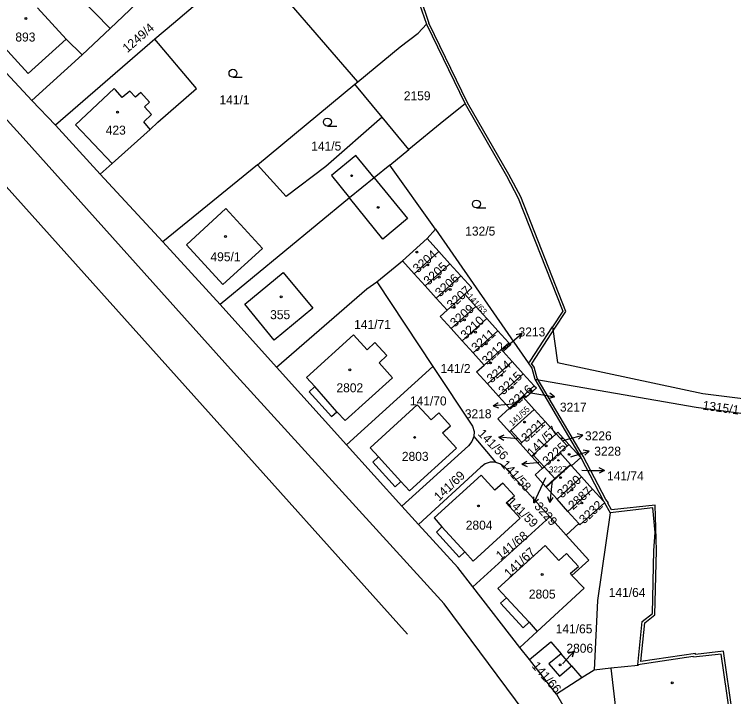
# Model space of a CAD drawing. Extents: x -866656 to -858817, y -1041816 to -1038653.
# Drawn here: x -866311.9 to -866175.7, y -1039421.3 to -1039292.1 of the extents above; entities that cross this region are included whole.
import ezdxf

# ---------------------------------------------------------------- set-up
doc = ezdxf.new("R2010")
doc.units = 0
for name, color, linetype in [('Hranice parcel', 7, 'Continuous'), ('Parcelní čísla', 7, 'Continuous'), ('Pop  PČ popisy', 7, 'Continuous'), ('Vnitřní kresba', 7, 'Continuous'), ('Značky budov', 7, 'Continuous'), ('Značky kultur', 7, 'Continuous')]:
    doc.layers.add(name, color=color, linetype=linetype)

msp = doc.modelspace()

# ---------------------------------------------------------------- linework, layer by layer
at = {"layer": 'Hranice parcel'}
for p, q in [((-866310.19, -1039315.5), (-866388.17, -1039229.96)), ((-866243.86, -1039264.43), (-866233.84, -1039293.98)), ((-866246.83, -1039304.89), (-866267.13, -1039281.27)), ((-866293.75, -1039294.78), (-866302.19, -1039286.07)), ((-866293.75, -1039294.78), (-866286.54, -1039287.95)), ((-866273.98, -1039287.22), (-866281.75, -1039293.82)), ((-866324.37, -1039291.52), (-866308.57, -1039308.43)), ((-866281.75, -1039293.82), (-866285.25, -1039296.84)), ((-866235.43, -1039295.7), (-866233.84, -1039293.98)), ((-866233.84, -1039293.98), (-866226.5, -1039309.08)), ((-866317.38, -1039294.43), (-866309.25, -1039303.3)), ((-866299.04, -1039299.78), (-866293.75, -1039294.78)), ((-866238.82, -1039298.26), (-866235.43, -1039295.7)), ((-866309.25, -1039303.3), (-866302.07, -1039296.79)), ((-866285.25, -1039296.84), (-866304.12, -1039313.11)), ((-866302.07, -1039296.79), (-866299.04, -1039299.78)), ((-866277.39, -1039306.13), (-866285.25, -1039296.84)), ((-866246.83, -1039304.89), (-866238.82, -1039298.26)), ((-866308.57, -1039308.43), (-866299.04, -1039299.78)), ((-866247.38, -1039305.34), (-866246.83, -1039304.89)), ((-866284.74, -1039312.51), (-866277.39, -1039306.13)), ((-866265.81, -1039320.6), (-866247.38, -1039305.34)), ((-866242.2, -1039311.59), (-866247.38, -1039305.34)), ((-866304.12, -1039313.11), (-866308.57, -1039308.43)), ((-866226.5, -1039309.08), (-866230.52, -1039312.29)), ((-866226.5, -1039309.08), (-866218.65, -1039322.67)), ((-866242.2, -1039311.59), (-866252.88, -1039320.93)), ((-866237.17, -1039317.71), (-866242.2, -1039311.59)), ((-866286.15, -1039313.91), (-866284.74, -1039312.51)), ((-866230.52, -1039312.29), (-866237.17, -1039317.71)), ((-866304.12, -1039313.11), (-866295.62, -1039322.36)), ((-866293.38, -1039320.36), (-866286.15, -1039313.91)), ((-866270.38, -1039359.88), (-866310.19, -1039315.5)), ((-866240.77, -1039320.64), (-866237.17, -1039317.71)), ((-866316.84, -1039320.96), (-866237.43, -1039409.44)), ((-866295.62, -1039322.36), (-866293.38, -1039320.36)), ((-866265.81, -1039320.6), (-866283.77, -1039335.19)), ((-866260.41, -1039326.6), (-866265.81, -1039320.6)), ((-866252.88, -1039320.93), (-866260.41, -1039326.6)), ((-866240.77, -1039320.64), (-866243.73, -1039323.05)), ((-866232.15, -1039332.75), (-866240.77, -1039320.64)), ((-866295.62, -1039322.36), (-866283.77, -1039335.19)), ((-866243.73, -1039323.05), (-866248.4, -1039326.86)), ((-866218.65, -1039322.67), (-866216.44, -1039326.88)), ((-866248.4, -1039326.86), (-866272.92, -1039347.03)), ((-866216.44, -1039326.88), (-866208.01, -1039348.3)), ((-866233.7, -1039334.53), (-866232.15, -1039332.75)), ((-866232.15, -1039332.75), (-866214.57, -1039358.1)), ((-866238.36, -1039338.78), (-866233.7, -1039334.53)), ((-866233.7, -1039334.53), (-866231.47, -1039337.01)), ((-866283.77, -1039335.19), (-866272.92, -1039347.03)), ((-866236.16, -1039341.22), (-866231.47, -1039337.01)), ((-866231.47, -1039337.01), (-866229.4, -1039339.31)), ((-866243.22, -1039342.74), (-866238.36, -1039338.78)), ((-866236.16, -1039341.22), (-866238.36, -1039338.78)), ((-866234.09, -1039343.52), (-866229.4, -1039339.31)), ((-866229.4, -1039339.31), (-866227.33, -1039341.62)), ((-866234.09, -1039343.52), (-866236.16, -1039341.22)), ((-866232.01, -1039345.83), (-866227.33, -1039341.62)), ((-866227.33, -1039341.62), (-866225.22, -1039343.89)), ((-866245.13, -1039344.04), (-866243.22, -1039342.74)), ((-866243.22, -1039342.74), (-866232.63, -1039358.74)), ((-866262.24, -1039358.91), (-866245.13, -1039344.04)), ((-866232.01, -1039345.83), (-866234.09, -1039343.52)), ((-866225.22, -1039343.89), (-866226.56, -1039345.09)), ((-866229.9, -1039348.1), (-866226.56, -1039345.09)), ((-866226.56, -1039345.09), (-866224.48, -1039347.39)), ((-866272.92, -1039347.03), (-866262.24, -1039358.91)), ((-866229.9, -1039348.1), (-866232.01, -1039345.83)), ((-866231.24, -1039349.3), (-866229.9, -1039348.1)), ((-866229.16, -1039351.6), (-866224.48, -1039347.39)), ((-866224.48, -1039347.39), (-866222.4, -1039349.69)), ((-866208.01, -1039348.3), (-866209.97, -1039351.26)), ((-866229.16, -1039351.6), (-866231.24, -1039349.3)), ((-866227.08, -1039353.9), (-866222.4, -1039349.69)), ((-866222.4, -1039349.69), (-866220.32, -1039351.99)), ((-866227.08, -1039353.9), (-866229.16, -1039351.6)), ((-866225, -1039356.2), (-866220.32, -1039351.99)), ((-866220.32, -1039351.99), (-866218.24, -1039354.29)), ((-866214.2, -1039357.79), (-866209.97, -1039351.26)), ((-866209.97, -1039351.26), (-866209.02, -1039358.03)), ((-866247.68, -1039352.75), (-866256.57, -1039360.83)), ((-866245.05, -1039355.62), (-866247.68, -1039352.75)), ((-866225, -1039356.2), (-866227.08, -1039353.9)), ((-866243.59, -1039354.25), (-866245.05, -1039355.62)), ((-866241.37, -1039356.71), (-866243.59, -1039354.25)), ((-866219.66, -1039355.54), (-866218.24, -1039354.29)), ((-866217.87, -1039354.6), (-866219.31, -1039355.92)), ((-866218.24, -1039354.29), (-866217.87, -1039354.6)), ((-866222.92, -1039358.49), (-866225, -1039356.2)), ((-866222.92, -1039358.49), (-866219.66, -1039355.54)), ((-866219.31, -1039355.92), (-866219.66, -1039355.54)), ((-866219.31, -1039355.92), (-866217.58, -1039357.84)), ((-866242.8, -1039358.06), (-866241.37, -1039356.71)), ((-866222.25, -1039362.07), (-866217.58, -1039357.84)), ((-866217.58, -1039357.84), (-866215.5, -1039360.14)), ((-866214.57, -1039358.1), (-866214.2, -1039357.79)), ((-866209.02, -1039358.03), (-866181.49, -1039363.87)), ((-866249, -1039373.58), (-866262.24, -1039358.91)), ((-866232.63, -1039358.74), (-866249, -1039373.58)), ((-866240.26, -1039360.9), (-866242.8, -1039358.06)), ((-866232.63, -1039358.74), (-866225.12, -1039370.08)), ((-866224.33, -1039359.77), (-866222.92, -1039358.49)), ((-866214.57, -1039358.1), (-866213.9, -1039359.11)), ((-866213.9, -1039359.11), (-866213.3, -1039361.19)), ((-866230.48, -1039403.71), (-866270.38, -1039359.88)), ((-866222.25, -1039362.07), (-866224.33, -1039359.77)), ((-866220.17, -1039364.37), (-866215.5, -1039360.14)), ((-866215.5, -1039360.14), (-866213.42, -1039362.44)), ((-866256.57, -1039360.83), (-866255, -1039362.57)), ((-866249.2, -1039369.02), (-866240.26, -1039360.9)), ((-866220.17, -1039364.37), (-866222.25, -1039362.07)), ((-866213.3, -1039361.19), (-866204.6, -1039375.99)), ((-866213.3, -1039361.19), (-866182.74, -1039366.49)), ((-866255, -1039362.57), (-866256.07, -1039363.56)), ((-866215.64, -1039364.45), (-866213.42, -1039362.44)), ((-866213.02, -1039362.81), (-866215.02, -1039364.62)), ((-866213.42, -1039362.44), (-866213.02, -1039362.81)), ((-866256.07, -1039363.56), (-866251.84, -1039368.26)), ((-866218.09, -1039366.67), (-866220.17, -1039364.37)), ((-866218.09, -1039366.67), (-866215.64, -1039364.45)), ((-866215.51, -1039364.6), (-866217.96, -1039366.82)), ((-866215.51, -1039364.6), (-866215.64, -1039364.45)), ((-866215.25, -1039364.37), (-866215.51, -1039364.6)), ((-866213.43, -1039366.9), (-866215.51, -1039364.6)), ((-866215.02, -1039364.62), (-866215.25, -1039364.37)), ((-866181.49, -1039363.87), (-866150.56, -1039367.7)), ((-866235.57, -1039366.05), (-866244.47, -1039374.16)), ((-866232.97, -1039368.85), (-866235.57, -1039366.05)), ((-866251.84, -1039368.26), (-866250.78, -1039367.33)), ((-866250.78, -1039367.33), (-866249.2, -1039369.02)), ((-866231.48, -1039367.56), (-866232.97, -1039368.85)), ((-866229.28, -1039370.02), (-866231.48, -1039367.56)), ((-866220.32, -1039368.68), (-866218.09, -1039366.67)), ((-866217.96, -1039366.82), (-866218.09, -1039366.67)), ((-866217.83, -1039370.88), (-866213.43, -1039366.9)), ((-866213.43, -1039366.9), (-866211.35, -1039369.2)), ((-866182.74, -1039366.49), (-866151.75, -1039370.52)), ((-866218.1, -1039371.12), (-866220.32, -1039368.68)), ((-866230.77, -1039371.35), (-866229.28, -1039370.02)), ((-866225.12, -1039370.08), (-866224.82, -1039371.05)), ((-866211.35, -1039369.2), (-866215.74, -1039373.17)), ((-866209.27, -1039371.49), (-866211.35, -1039369.2)), ((-866228.16, -1039374.22), (-866230.77, -1039371.35)), ((-866224.82, -1039371.05), (-866224.86, -1039372.05)), ((-866218.1, -1039371.12), (-866217.83, -1039370.88)), ((-866216.02, -1039373.42), (-866218.1, -1039371.12)), ((-866215.74, -1039373.17), (-866217.83, -1039370.88)), ((-866213.65, -1039375.46), (-866209.27, -1039371.49)), ((-866209.27, -1039371.49), (-866208.97, -1039371.22)), ((-866207.19, -1039373.79), (-866209.27, -1039371.49)), ((-866208.97, -1039371.22), (-866206.88, -1039373.51)), ((-866225.22, -1039372.99), (-866225.88, -1039373.76)), ((-866224.86, -1039372.05), (-866225.22, -1039372.99)), ((-866224.86, -1039372.05), (-866220.77, -1039376.85)), ((-866238.47, -1039385.18), (-866249, -1039373.58)), ((-866244.47, -1039374.16), (-866242.9, -1039375.89)), ((-866225.88, -1039373.76), (-866238.47, -1039385.18)), ((-866237.06, -1039382.29), (-866228.16, -1039374.22)), ((-866216.02, -1039373.42), (-866215.74, -1039373.17)), ((-866213.94, -1039375.72), (-866216.02, -1039373.42)), ((-866208.6, -1039375.07), (-866207.19, -1039373.79)), ((-866207.19, -1039373.79), (-866206.88, -1039373.51)), ((-866206.88, -1039373.51), (-866204.6, -1039375.99)), ((-866213.94, -1039375.72), (-866213.65, -1039375.46)), ((-866211.86, -1039378.02), (-866213.94, -1039375.72)), ((-866211.56, -1039377.75), (-866213.65, -1039375.46)), ((-866211.56, -1039377.75), (-866208.6, -1039375.07)), ((-866206.58, -1039377.3), (-866208.6, -1039375.07)), ((-866242.9, -1039375.89), (-866243.99, -1039376.9)), ((-866243.99, -1039376.9), (-866239.75, -1039381.55)), ((-866221.77, -1039376.86), (-866222.73, -1039377.22)), ((-866220.77, -1039376.85), (-866221.77, -1039376.86)), ((-866220.77, -1039376.85), (-866219.83, -1039377.19)), ((-866204.6, -1039375.99), (-866206.34, -1039377.57)), ((-866204.6, -1039375.99), (-866200.28, -1039384.26)), ((-866223.51, -1039377.82), (-866235.33, -1039388.65)), ((-866222.73, -1039377.22), (-866223.51, -1039377.82)), ((-866219.83, -1039377.19), (-866219.02, -1039377.84)), ((-866219.02, -1039377.84), (-866210.49, -1039387.25)), ((-866213.27, -1039379.3), (-866211.86, -1039378.02)), ((-866211.86, -1039378.02), (-866211.56, -1039377.75)), ((-866209.54, -1039379.97), (-866211.56, -1039377.75)), ((-866211.19, -1039381.59), (-866206.52, -1039377.37)), ((-866209.54, -1039379.97), (-866206.58, -1039377.3)), ((-866206.52, -1039377.37), (-866206.58, -1039377.3)), ((-866206.34, -1039377.57), (-866206.52, -1039377.37)), ((-866204.44, -1039379.66), (-866206.34, -1039377.57)), ((-866223.48, -1039379.34), (-866232.4, -1039387.42)), ((-866220.87, -1039382.15), (-866223.48, -1039379.34)), ((-866211.25, -1039381.53), (-866213.27, -1039379.3)), ((-866204.44, -1039379.66), (-866209.11, -1039383.89)), ((-866202.36, -1039381.96), (-866204.44, -1039379.66)), ((-866239.75, -1039381.55), (-866238.66, -1039380.53)), ((-866238.66, -1039380.53), (-866237.06, -1039382.29)), ((-866219.4, -1039380.86), (-866220.87, -1039382.15)), ((-866217.17, -1039383.26), (-866219.4, -1039380.86)), ((-866211.25, -1039381.53), (-866209.54, -1039379.97)), ((-866211.19, -1039381.59), (-866211.25, -1039381.53)), ((-866209.11, -1039383.89), (-866211.19, -1039381.59)), ((-866207.03, -1039386.19), (-866202.36, -1039381.96)), ((-866202.36, -1039381.96), (-866200.28, -1039384.26)), ((-866218.71, -1039384.56), (-866217.17, -1039383.26)), ((-866207.03, -1039386.19), (-866209.11, -1039383.89)), ((-866235.33, -1039388.65), (-866238.47, -1039385.18)), ((-866216.06, -1039387.48), (-866218.71, -1039384.56)), ((-866200.12, -1039384.55), (-866204.8, -1039388.73)), ((-866200.28, -1039384.26), (-866200.06, -1039384.5)), ((-866200.06, -1039384.5), (-866200.12, -1039384.55)), ((-866200.12, -1039384.55), (-866199.07, -1039386.46)), ((-866204.95, -1039388.49), (-866207.03, -1039386.19)), ((-866199.07, -1039386.46), (-866201.43, -1039403.06)), ((-866190.99, -1039385.55), (-866199.07, -1039386.46)), ((-866190.53, -1039390.22), (-866190.99, -1039385.55)), ((-866232.4, -1039387.42), (-866230.9, -1039389.15)), ((-866210.49, -1039387.25), (-866225.06, -1039400.48)), ((-866224.97, -1039395.59), (-866216.06, -1039387.48)), ((-866210.49, -1039387.25), (-866207.37, -1039390.68)), ((-866227.92, -1039396.82), (-866235.33, -1039388.65)), ((-866230.9, -1039389.15), (-866231.91, -1039390.16)), ((-866207.37, -1039390.68), (-866204.95, -1039388.49)), ((-866204.8, -1039388.73), (-866204.95, -1039388.49)), ((-866231.91, -1039390.16), (-866227.65, -1039394.84)), ((-866207.37, -1039390.68), (-866203.09, -1039395.4)), ((-866190.77, -1039393.59), (-866190.53, -1039390.22)), ((-866211.37, -1039392.68), (-866220.32, -1039400.77)), ((-866208.79, -1039395.52), (-866211.37, -1039392.68)), ((-866227.65, -1039394.84), (-866226.54, -1039393.86)), ((-866226.54, -1039393.86), (-866224.97, -1039395.59)), ((-866207.32, -1039394.17), (-866208.79, -1039395.52)), ((-866205.07, -1039396.62), (-866207.32, -1039394.17)), ((-866191.05, -1039405.53), (-866190.77, -1039393.59)), ((-866203.09, -1039395.4), (-866206.31, -1039398.32)), ((-866225.06, -1039400.48), (-866227.92, -1039396.82)), ((-866206.57, -1039397.9), (-866205.07, -1039396.62)), ((-866206.31, -1039398.32), (-866206.57, -1039397.9)), ((-866203.95, -1039400.75), (-866206.31, -1039398.32)), ((-866216.12, -1039411.94), (-866225.06, -1039400.48)), ((-866220.32, -1039400.77), (-866218.69, -1039402.54)), ((-866212.84, -1039408.95), (-866203.95, -1039400.75)), ((-866218.69, -1039402.54), (-866219.8, -1039403.55)), ((-866215.35, -1039424.06), (-866230.48, -1039403.71)), ((-866219.8, -1039403.55), (-866215.54, -1039408.21)), ((-866201.43, -1039403.06), (-866202.07, -1039416.25)), ((-866192.95, -1039407.03), (-866191.05, -1039405.53)), ((-866193.78, -1039415.23), (-866192.95, -1039407.03)), ((-866215.54, -1039408.21), (-866214.4, -1039407.15)), ((-866214.4, -1039407.15), (-866212.84, -1039408.95)), ((-866212.84, -1039408.95), (-866216.12, -1039411.94)), ((-866214.31, -1039414.26), (-866210.31, -1039410.87)), ((-866210.31, -1039410.87), (-866208.35, -1039413.14)), ((-866214.31, -1039414.26), (-866216.12, -1039411.94)), ((-866208.35, -1039413.14), (-866210.63, -1039415.08)), ((-866206.39, -1039415.41), (-866208.35, -1039413.14)), ((-866183.31, -1039413.68), (-866193.78, -1039415.23)), ((-866183.29, -1039413.82), (-866183.31, -1039413.68)), ((-866178, -1039413.2), (-866183.29, -1039413.82)), ((-866176.29, -1039425.23), (-866178, -1039413.2)), ((-866209.21, -1039420.78), (-866214.31, -1039414.26)), ((-866210.63, -1039415.08), (-866208.66, -1039417.36)), ((-866193.78, -1039415.23), (-866193.76, -1039415.38)), ((-866208.66, -1039417.36), (-866206.39, -1039415.41)), ((-866206.39, -1039415.41), (-866204.39, -1039417.72)), ((-866202.07, -1039416.25), (-866204.39, -1039417.72)), ((-866198.89, -1039415.9), (-866202.07, -1039416.25)), ((-866193.76, -1039415.38), (-866198.89, -1039415.9)), ((-866204.39, -1039417.72), (-866209.21, -1039420.78)), ((-866209.21, -1039420.78), (-866198.34, -1039439.58))]:
    msp.add_line(p, q, dxfattribs=at)
at = {"layer": 'Pop  PČ popisy'}
for p, q in [((-866218.03, -1039354.47), (-866215.77, -1039352.5)), ((-866215.77, -1039352.5), (-866216.85, -1039352.78)), ((-866215.77, -1039352.5), (-866216.19, -1039353.54)), ((-866218.64, -1039355), (-866218.03, -1039354.47)), ((-866214.42, -1039363.72), (-866212.52, -1039364.02)), ((-866212.52, -1039364.02), (-866209.56, -1039364.49)), ((-866209.56, -1039364.49), (-866210.62, -1039364.83)), ((-866209.56, -1039364.49), (-866210.47, -1039363.84)), ((-866221.21, -1039366.2), (-866220.26, -1039365.61)), ((-866218.22, -1039365.94), (-866221.21, -1039366.2)), ((-866221.21, -1039366.2), (-866220.17, -1039366.61)), ((-866217.06, -1039365.85), (-866218.22, -1039365.94)), ((-866204.19, -1039371.75), (-866205.29, -1039371.53)), ((-866220.15, -1039372.12), (-866219.1, -1039371.72)), ((-866217.16, -1039372.43), (-866220.15, -1039372.12)), ((-866220.15, -1039372.12), (-866219.2, -1039372.72)), ((-866216.62, -1039372.49), (-866217.16, -1039372.43)), ((-866207.9, -1039372.75), (-866207.09, -1039372.53)), ((-866207.09, -1039372.53), (-866204.19, -1039371.75)), ((-866204.19, -1039371.75), (-866205.03, -1039372.5)), ((-866206.5, -1039375.87), (-866205.92, -1039375.69)), ((-866205.92, -1039375.69), (-866203.05, -1039374.81)), ((-866203.05, -1039374.81), (-866204.15, -1039374.63)), ((-866203.05, -1039374.81), (-866203.86, -1039375.58)), ((-866215.8, -1039377.27), (-866214.85, -1039376.69)), ((-866212.81, -1039377.01), (-866215.8, -1039377.27)), ((-866212.56, -1039376.99), (-866212.81, -1039377.01)), ((-866215.8, -1039377.27), (-866214.76, -1039377.68)), ((-866204.43, -1039378.41), (-866203.13, -1039378.43)), ((-866203.13, -1039378.43), (-866200.13, -1039378.48)), ((-866200.13, -1039378.48), (-866201.12, -1039377.96)), ((-866200.13, -1039378.48), (-866201.14, -1039378.97)), ((-866211.3, -1039379.87), (-866212.21, -1039381.86)), ((-866210.03, -1039380.48), (-866210.14, -1039381.51)), ((-866212.21, -1039381.86), (-866213.48, -1039384.58)), ((-866210.14, -1039381.51), (-866210.45, -1039384.49)), ((-866213.48, -1039384.58), (-866213.51, -1039383.46)), ((-866213.48, -1039384.58), (-866212.6, -1039383.88)), ((-866210.45, -1039384.49), (-866210.85, -1039383.45)), ((-866210.45, -1039384.49), (-866209.85, -1039383.55)), ((-866207.94, -1039414.93), (-866205.93, -1039412.7)), ((-866205.93, -1039412.7), (-866206.97, -1039413.11)), ((-866205.93, -1039412.7), (-866206.23, -1039413.78)), ((-866208.02, -1039415.02), (-866207.94, -1039414.93))]:
    msp.add_line(p, q, dxfattribs=at)
at = {"layer": 'Vnitřní kresba'}
for p, q in [((-866243.39, -1039264.27), (-866233.39, -1039293.76)), ((-866302.07, -1039296.79), (-866307.47, -1039290.88)), ((-866226.06, -1039308.85), (-866233.39, -1039293.76)), ((-866292.95, -1039306.14), (-866300.28, -1039313.03)), ((-866292.74, -1039306.39), (-866292.95, -1039306.14)), ((-866291.45, -1039307.87), (-866292.74, -1039306.39)), ((-866290.01, -1039306.63), (-866291.45, -1039307.87)), ((-866288.92, -1039307.8), (-866290.01, -1039306.63)), ((-866287.93, -1039306.9), (-866288.92, -1039307.8)), ((-866286.27, -1039308.71), (-866287.93, -1039306.9)), ((-866287.26, -1039309.62), (-866286.27, -1039308.71)), ((-866218.21, -1039322.43), (-866226.06, -1039308.85)), ((-866285.92, -1039311.08), (-866287.26, -1039309.62)), ((-866287.33, -1039312.48), (-866285.92, -1039311.08)), ((-866300.28, -1039313.03), (-866293.38, -1039320.36)), ((-866286.15, -1039313.91), (-866287.33, -1039312.48)), ((-866247.19, -1039318.81), (-866251.83, -1039322.6)), ((-866243.73, -1039323.05), (-866247.19, -1039318.81)), ((-866251.83, -1039322.6), (-866248.4, -1039326.86)), ((-866215.98, -1039326.67), (-866218.21, -1039322.43)), ((-866243.73, -1039323.05), (-866237.43, -1039330.78)), ((-866207.45, -1039348.36), (-866215.98, -1039326.67)), ((-866242.11, -1039334.68), (-866248.4, -1039326.86)), ((-866279.26, -1039335.77), (-866271.84, -1039328.87)), ((-866271.84, -1039328.87), (-866264.91, -1039336.46)), ((-866237.43, -1039330.78), (-866242.11, -1039334.68)), ((-866272.41, -1039343.24), (-866279.26, -1039335.77)), ((-866264.91, -1039336.46), (-866272.41, -1039343.24)), ((-866268.24, -1039346.98), (-866260.96, -1039340.96)), ((-866260.96, -1039340.96), (-866255.33, -1039347.73)), ((-866262.65, -1039353.81), (-866268.24, -1039346.98)), ((-866255.33, -1039347.73), (-866262.65, -1039353.81)), ((-866209.55, -1039351.53), (-866207.45, -1039348.36)), ((-866213.82, -1039358.12), (-866209.55, -1039351.53)), ((-866213.91, -1039358.2), (-866213.82, -1039358.12)), ((-866213.44, -1039358.9), (-866213.91, -1039358.2)), ((-866212.84, -1039360.99), (-866213.44, -1039358.9)), ((-866204.16, -1039375.75), (-866212.84, -1039360.99)), ((-866250.78, -1039367.33), (-866255, -1039362.57)), ((-866238.66, -1039380.53), (-866242.9, -1039375.89)), ((-866199.87, -1039383.97), (-866204.16, -1039375.75)), ((-866199.34, -1039384.55), (-866199.87, -1039383.97)), ((-866199.48, -1039384.67), (-866199.34, -1039384.55)), ((-866198.79, -1039385.93), (-866199.48, -1039384.67)), ((-866190.51, -1039384.99), (-866198.79, -1039385.93)), ((-866190.27, -1039393.59), (-866190.51, -1039384.99)), ((-866230.9, -1039389.15), (-866226.54, -1039393.86)), ((-866190.56, -1039405.78), (-866190.27, -1039393.59)), ((-866214.4, -1039407.15), (-866218.69, -1039402.54)), ((-866192.47, -1039407.29), (-866190.56, -1039405.78)), ((-866193.22, -1039414.64), (-866192.47, -1039407.29)), ((-866182.89, -1039413.11), (-866193.22, -1039414.64)), ((-866182.86, -1039413.27), (-866182.89, -1039413.11)), ((-866177.57, -1039412.65), (-866182.86, -1039413.27)), ((-866175.78, -1039425.23), (-866177.57, -1039412.65)), ((-866198.89, -1039415.9), (-866197.51, -1039428.3))]:
    msp.add_line(p, q, dxfattribs=at)
at = {"layer": 'Značky budov'}
for centre, radius in [((-866309.69, -1039292.9), 0.175), ((-866292.32, -1039310.62), 0.175), ((-866248, -1039322.66), 0.175), ((-866242.97, -1039328.65), 0.175), ((-866271.91, -1039334.17), 0.175), ((-866235.64, -1039337.11), 0.175), ((-866233.6, -1039339.55), 0.175), ((-866231.43, -1039341.86), 0.175), ((-866229.34, -1039344.18), 0.175), ((-866261.35, -1039345.59), 0.175), ((-866228.6, -1039347.58), 0.175), ((-866226.65, -1039349.93), 0.175), ((-866224.56, -1039352.28), 0.175), ((-866222.5, -1039354.49), 0.175), ((-866218.93, -1039355.22), 0.175), ((-866221.72, -1039358.1), 0.175), ((-866248.33, -1039359.39), 0.175), ((-866219.59, -1039360.43), 0.175), ((-866217.61, -1039362.75), 0.175), ((-866214.09, -1039363.4), 0.175), ((-866216.72, -1039365.57), 0.117), ((-866215.24, -1039369.29), 0.175), ((-866236.07, -1039372.19), 0.175), ((-866208.19, -1039372.38), 0.117), ((-866211.19, -1039373.8), 0.175), ((-866206.79, -1039375.4), 0.175), ((-866208.84, -1039376.54), 0.117), ((-866208.42, -1039379.81), 0.175), ((-866206.28, -1039382.13), 0.175), ((-866224, -1039385.17), 0.175), ((-866204.39, -1039384.61), 0.175), ((-866211.91, -1039398.14), 0.175), ((-866208.54, -1039415.24), 0.175), ((-866187.28, -1039418.65), 0.175)]:
    msp.add_circle(centre, radius, dxfattribs=at)
at = {"layer": 'Značky kultur'}
for p, q in [((-866270.48, -1039304.02), (-866268.73, -1039304.02)), ((-866252.59, -1039313.26), (-866250.84, -1039313.26)), ((-866224.37, -1039328.76), (-866222.62, -1039328.76))]:
    msp.add_line(p, q, dxfattribs=at)
for centre in [(-866270.48, -1039303.27), (-866252.59, -1039312.51), (-866224.37, -1039328.01)]:
    msp.add_circle(centre, 0.75, dxfattribs=at)

# ---------------------------------------------------------------- texts
at = {"layer": 'Parcelní čísla'}
for s, height, rotation, p in [('1249/4', 1.7, 41, (-866290.48, -1039299.47)), ('3204', 1.7, 41, (-866235.51, -1039341.16)), ('3205', 1.7, 42, (-866233.46, -1039343.49)), ('3206', 1.7, 42, (-866231.27, -1039345.71)), ('3207', 1.7, 42, (-866229.05, -1039348.01)), ('141/63', 1.14, 312, (-866226.22, -1039345.59)), ('3209', 1.7, 41, (-866228.46, -1039351.41)), ('3210', 1.7, 43, (-866226.43, -1039353.73)), ('3211', 1.7, 41, (-866224.43, -1039356.11)), ('3212', 1.7, 43, (-866222.39, -1039358.59)), ('3214', 1.7, 40, (-866221.53, -1039361.99)), ('3215', 1.7, 43, (-866219.26, -1039364.26)), ('3216', 1.7, 41, (-866217.34, -1039366.68)), ('1315/1', 1.7, 352, (-866181.62, -1039366.91)), ('141/55', 1.14, 43, (-866217.56, -1039370.16)), ('3221', 1.7, 43, (-866214.94, -1039373.23)), ('141/57', 1.7, 45, (-866213.76, -1039375.96)), ('141/56', 1.7, 314, (-866224.22, -1039371.6)), ('3225', 1.7, 42, (-866210.93, -1039377.63)), ('141/58', 1.7, 313, (-866219.83, -1039377.46)), ('141/69', 1.7, 43, (-866231.46, -1039384.35)), ('3230', 1.7, 41, (-866208.18, -1039383.79)), ('2887', 1.7, 42, (-866206.07, -1039386)), ('141/59', 1.7, 316, (-866218.7, -1039384.56)), ('3229', 1.7, 312, (-866213.53, -1039385.33)), ('3232', 1.7, 43, (-866203.97, -1039388.67)), ('141/68', 1.7, 39, (-866219.82, -1039395.49)), ('141/67', 1.7, 43, (-866218.17, -1039398.84)), ('141/66', 1.7, 311, (-866213.99, -1039415.53))]:
    msp.add_text(s, height=height, rotation=rotation, dxfattribs=at).set_placement(p)
for s, height, p in [('893', 1.7, (-866311.69, -1039297.26)), ('141/1', 1.7, (-866273.04, -1039309.15)), ('2159', 1.7, (-866238.12, -1039308.38)), ('423', 1.7, (-866294.57, -1039314.88)), ('141/5', 1.7, (-866255.66, -1039317.9)), ('132/5', 1.7, (-866226.49, -1039333.99)), ('495/1', 1.7, (-866274.74, -1039338.85)), ('355', 1.7, (-866263.44, -1039349.81)), ('141/71', 1.7, (-866247.53, -1039351.66)), ('3213', 1.7, (-866216.39, -1039353.08)), ('141/2', 1.7, (-866231.17, -1039360)), ('2802', 1.7, (-866250.88, -1039363.65)), ('141/70', 1.7, (-866236.97, -1039366.14)), ('3217', 1.7, (-866208.56, -1039367.31)), ('3218', 1.7, (-866226.57, -1039368.57)), ('3226', 1.7, (-866203.81, -1039372.75)), ('3228', 1.7, (-866202.05, -1039375.65)), ('2803', 1.7, (-866238.49, -1039376.63)), ('3227', 1.14, (-866210.64, -1039378.83)), ('141/74', 1.7, (-866199.64, -1039380.34)), ('2804', 1.7, (-866226.39, -1039389.65)), ('2805', 1.7, (-866214.44, -1039402.7)), ('141/64', 1.7, (-866199.31, -1039402.39)), ('141/65', 1.7, (-866209.36, -1039409.28)), ('2806', 1.7, (-866207.33, -1039412.95))]:
    msp.add_text(s, height=height, dxfattribs=at).set_placement(p)

doc.saveas('drawing.dxf')
